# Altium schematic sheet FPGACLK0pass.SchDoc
size D
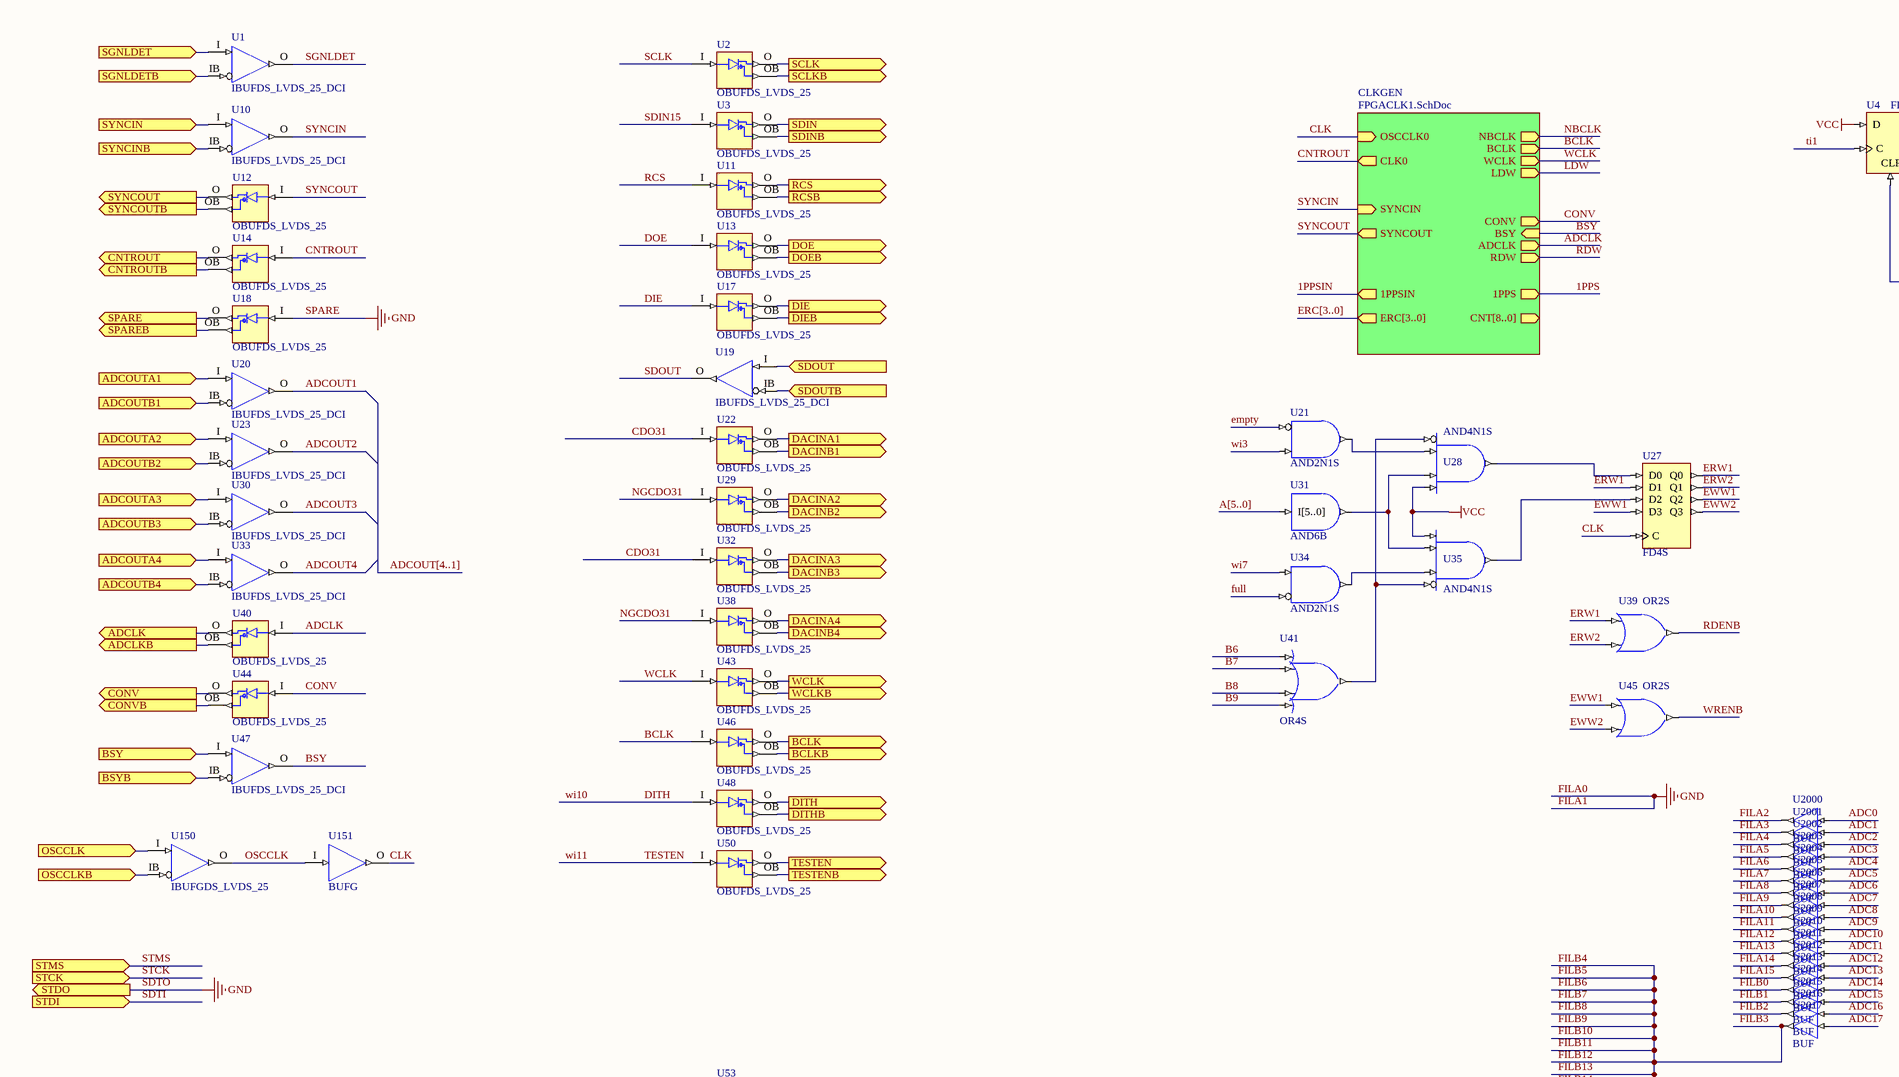
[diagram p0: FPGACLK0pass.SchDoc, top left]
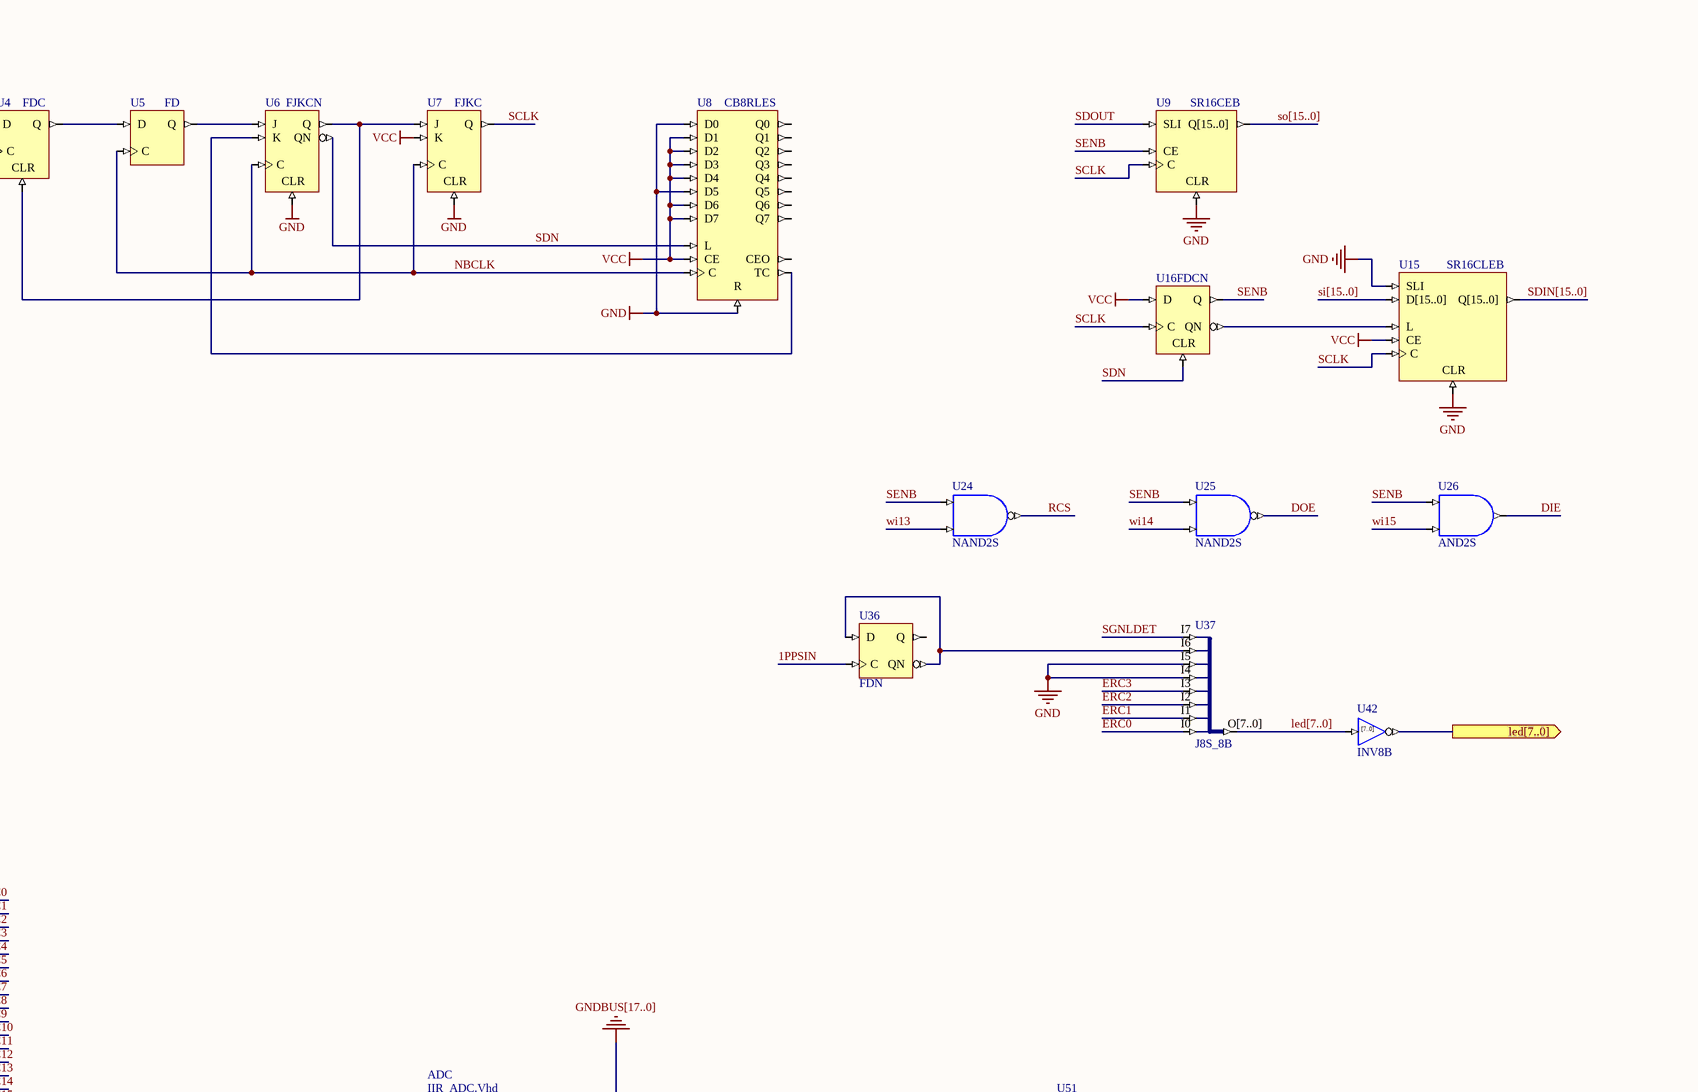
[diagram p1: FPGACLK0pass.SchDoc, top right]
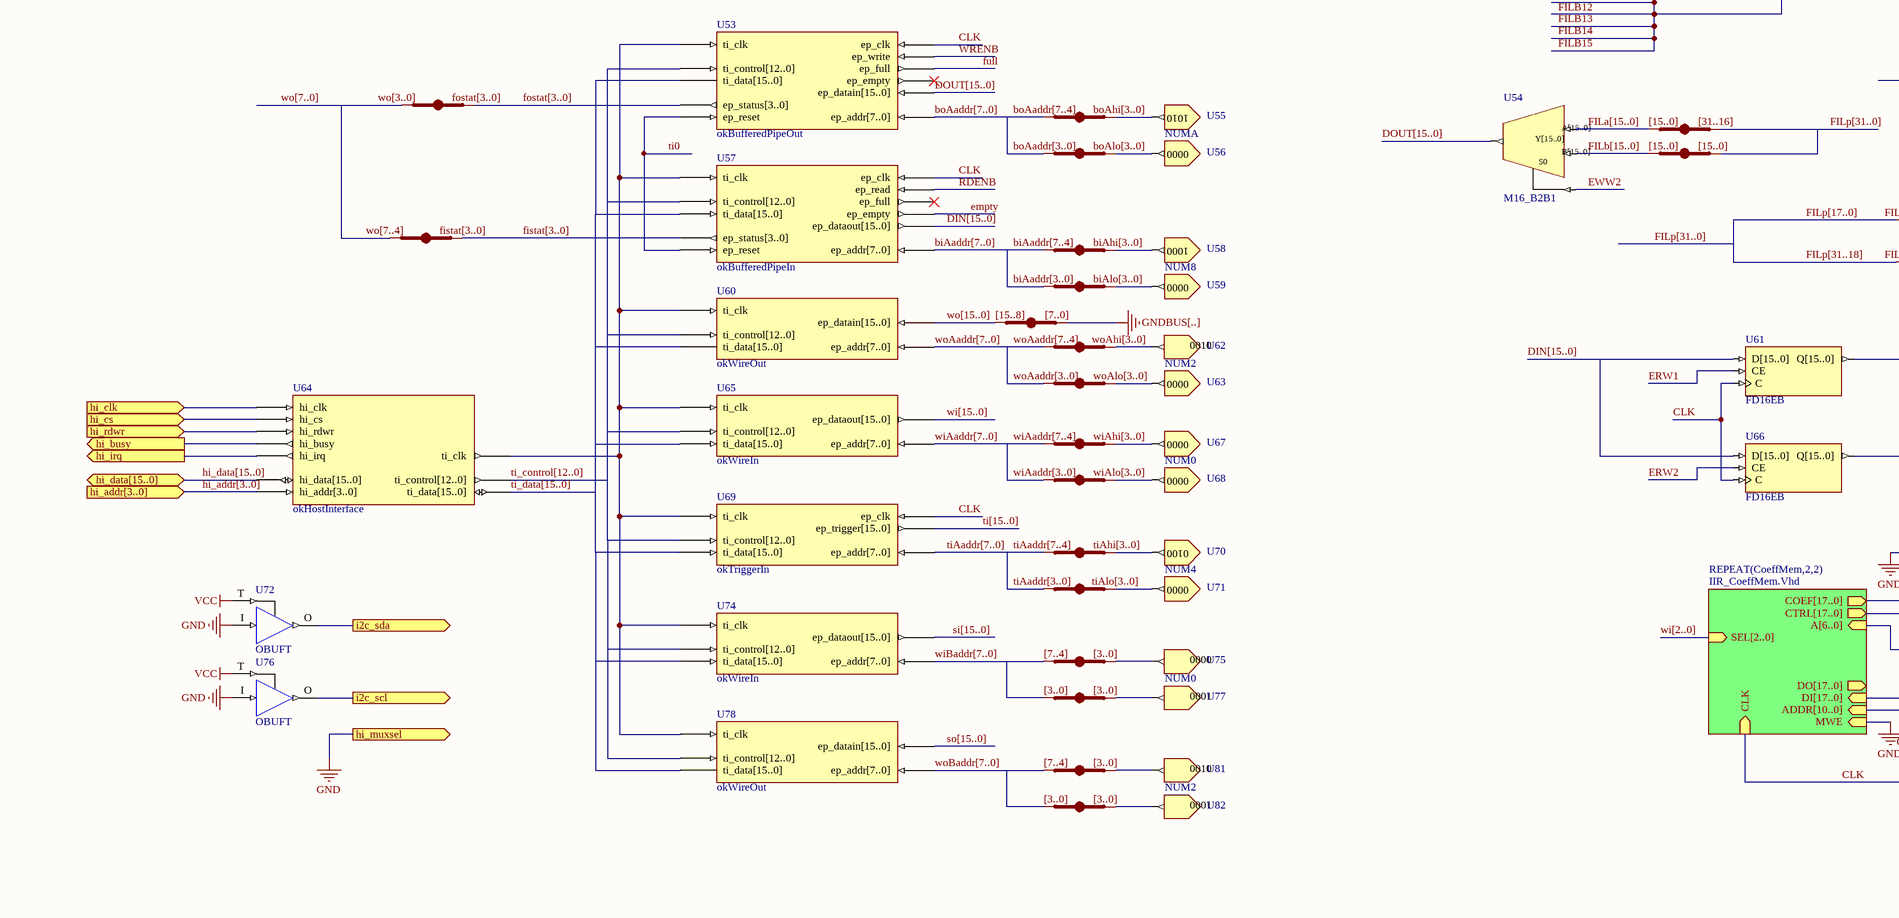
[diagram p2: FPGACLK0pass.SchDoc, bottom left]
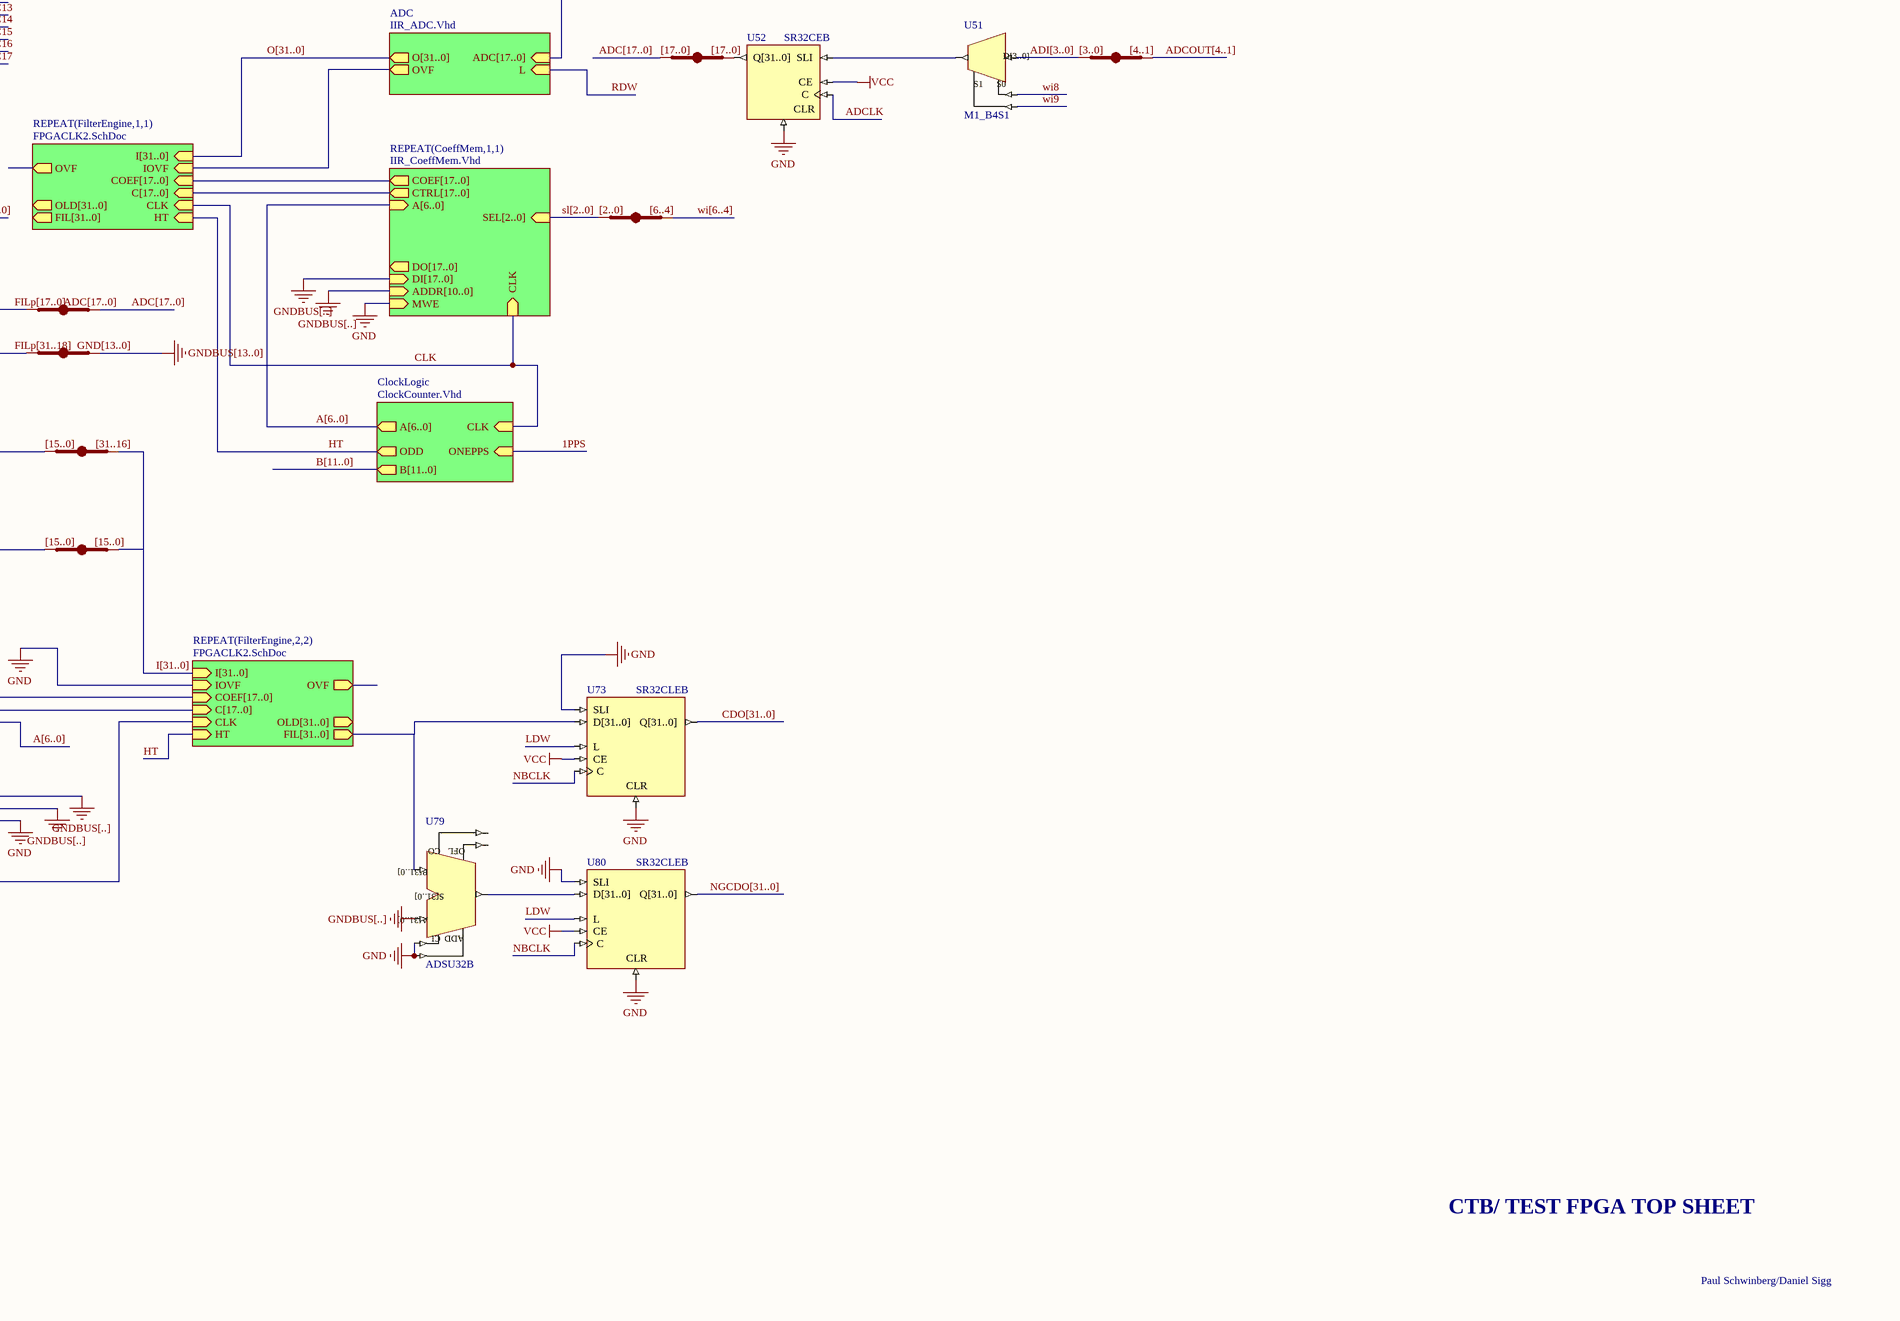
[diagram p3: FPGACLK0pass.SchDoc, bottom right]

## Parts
(Parts that share a designator on the sheet are numbered #1, #2 ... from top to bottom, then left to right.)
JB_AUTO?#1  IndexA: FILp[17..0]  IndexB: ADC[17..0]  (hidden comment: JB)
JB_AUTO?#2  IndexA: FILp[31..18]  IndexB: GND[13..0]  (hidden comment: JB)
JB_C1  IndexA: [17..0]  (hidden comment: JB)
JB_C2  IndexA: [3..0]  IndexB: [4..1]  (hidden comment: JB)
JB_C3  IndexA: wo[3..0]  IndexB: fostat[3..0]  (hidden comment: JB)
JB_C4  IndexA: boAaddr[7..4]  IndexB: boAhi[3..0]  (hidden comment: JB)
JB_C5  IndexA: [15..0]  IndexB: [31..16]  (hidden comment: JB)
JB_C6  IndexA: [2..0]  IndexB: [6..4]  (hidden comment: JB)
JB_C7  IndexA: boAaddr[3..0]  IndexB: boAlo[3..0]  (hidden comment: JB)
JB_C8  IndexA: [15..0]  (hidden comment: JB)
JB_C9  IndexA: wo[7..4]  IndexB: fistat[3..0]  (hidden comment: JB)
JB_C10  IndexA: biAaddr[7..4]  IndexB: biAhi[3..0]  (hidden comment: JB)
JB_C11  IndexA: biAaddr[3..0]  IndexB: biAlo[3..0]  (hidden comment: JB)
JB_C12#1  IndexA: [15..8]  IndexB: [7..0]  (hidden comment: JB)
JB_C12#2  IndexA: [15..0]  IndexB: [31..16]  (hidden comment: JB)
JB_C13  IndexA: woAaddr[7..4]  IndexB: woAhi[3..0]  (hidden comment: JB)
JB_C15  IndexA: woAaddr[3..0]  IndexB: woAlo[3..0]  (hidden comment: JB)
JB_C16  IndexA: wiAaddr[7..4]  IndexB: wiAhi[3..0]  (hidden comment: JB)
JB_C17  IndexA: [15..0]  (hidden comment: JB)
JB_C18  IndexA: wiAaddr[3..0]  IndexB: wiAlo[3..0]  (hidden comment: JB)
JB_C19  IndexA: tiAaddr[7..4]  IndexB: tiAhi[3..0]  (hidden comment: JB)
JB_C20  IndexA: tiAaddr[3..0]  IndexB: tiAlo[3..0]  (hidden comment: JB)
JB_C21  IndexA: [7..4]  IndexB: [3..0]  (hidden comment: JB)
JB_C22  IndexA: [3..0]  (hidden comment: JB)
JB_C23  IndexA: [7..4]  IndexB: [3..0]  (hidden comment: JB)
JB_C24  IndexA: [3..0]  (hidden comment: JB)
U1  IBUFDS_LVDS_25_DCI
U2  OBUFDS_LVDS_25
U3  OBUFDS_LVDS_25
U4  FDC
U5  FD
U6  FJKCN
U7  FJKC
U8  CB8RLES
U9  SR16CEB
U10  IBUFDS_LVDS_25_DCI
U11  OBUFDS_LVDS_25
U12  OBUFDS_LVDS_25
U13  OBUFDS_LVDS_25
U14  OBUFDS_LVDS_25
U15  SR16CLEB
U16  FDCN
U17  OBUFDS_LVDS_25
U18  OBUFDS_LVDS_25
U19  IBUFDS_LVDS_25_DCI
U20  IBUFDS_LVDS_25_DCI
U21  AND2N1S
U22  OBUFDS_LVDS_25
U23  IBUFDS_LVDS_25_DCI
U24  NAND2S
U25  NAND2S
U26  AND2S
U27  FD4S
U28  AND4N1S
U29  OBUFDS_LVDS_25
U30  IBUFDS_LVDS_25_DCI
U31  AND6B
U32  OBUFDS_LVDS_25
U33  IBUFDS_LVDS_25_DCI
U34  AND2N1S
U35  AND4N1S
U36  FDN
U37  J8S_8B
U38  OBUFDS_LVDS_25
U39  OR2S
U40  OBUFDS_LVDS_25
U41  OR4S
U42  INV8B
U43  OBUFDS_LVDS_25
U44  OBUFDS_LVDS_25
U45  OR2S
U46  OBUFDS_LVDS_25
U47  IBUFDS_LVDS_25_DCI
U48  OBUFDS_LVDS_25
U50  OBUFDS_LVDS_25
U51  M1_B4S1
U52  SR32CEB
U53  okBufferedPipeOut
U54  M16_B2B1
U55  NUMA
U56  NUM0  (value not drawn)
U57  okBufferedPipeIn
U58  NUM8
U59  NUM0  (value not drawn)
U60  okWireOut
U61  FD16EB
U62  NUM2
U63  NUM0  (value not drawn)
U64  okHostInterface
U65  okWireIn
U66  FD16EB
U67  NUM0
U68  NUM0  (value not drawn)
U69  okTriggerIn
U70  NUM4
U71  NUM0  (value not drawn)
U72  OBUFT
U73  SR32CLEB
U74  okWireIn
U75  NUM0
U76  OBUFT
U77  NUM1  (value not drawn)
U78  okWireOut
U79  ADSU32B
U80  SR32CLEB
U81  NUM2
U82  NUM1  (value not drawn)
U150  IBUFGDS_LVDS_25
U151  BUFG
U2000  BUF
U2001  BUF
U2002  BUF
U2003  BUF
U2004  BUF
U2005  BUF
U2006  BUF
U2007  BUF
U2008  BUF
U2009  BUF
U2010  BUF
U2011  BUF
U2012  BUF
U2013  BUF
U2014  BUF
U2015  BUF
U2016  BUF
U2017  BUF

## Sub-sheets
ADC = IIR_ADC.Vhd: ADC[17..0] (in), O[31..0] (out), L (in), OVF (out)
CLKGEN = FPGACLK1.SchDoc: SYNCIN (in), OSCCLK0 (in), CLK0 (out), SYNCOUT (out), BCLK (out), WCLK (out), LDW (out), CONV (out), BSY (in), ADCLK (out), RDW (out), NBCLK (out), 1PPS (out), 1PPSIN (out), ERC[3..0] (out), CNT[8..0] (out)
ClockLogic = ClockCounter.Vhd: CLK (in), ONEPPS (in), A[6..0] (out), ODD (out), B[11..0] (out)
REPEAT(CoeffMem,1,1) = IIR_CoeffMem.Vhd: CLK (in), A[6..0] (in), COEF[17..0] (out), CTRL[17..0] (out), SEL[2..0] (in), DI[17..0] (in), DO[17..0] (out), MWE (in), ADDR[10..0] (in)
REPEAT(CoeffMem,2,2) = IIR_CoeffMem.Vhd: CLK (in), A[6..0] (in), COEF[17..0] (out), CTRL[17..0] (out), SEL[2..0] (in), DI[17..0] (in), DO[17..0] (out), MWE (in), ADDR[10..0] (in)
REPEAT(FilterEngine,1,1) = FPGACLK2.SchDoc: CLK (in), FIL[31..0] (out), I[31..0] (in), C[17..0] (in), COEF[17..0] (in), HT (in), OLD[31..0] (out), OVF (out), IOVF (in)
REPEAT(FilterEngine,2,2) = FPGACLK2.SchDoc: CLK (in), FIL[31..0] (out), I[31..0] (in), C[17..0] (in), COEF[17..0] (in), HT (in), OLD[31..0] (out), OVF (out), IOVF (in)

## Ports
ADCLK (out), ADCLKB (out), ADCOUTA1 (in), ADCOUTA2 (in), ADCOUTA3 (in), ADCOUTA4 (in), ADCOUTB1 (in), ADCOUTB2 (in), ADCOUTB3 (in), ADCOUTB4 (in), BCLK (out), BCLKB (out), BSY (in), BSYB (in), CNTROUT (out), CNTROUTB (out), CONV (out), CONVB (out), DACINA1 (out), DACINA2 (out), DACINA3 (out), DACINA4 (out), DACINB1 (out), DACINB2 (out), DACINB3 (out), DACINB4 (out), DIE (out), DIEB (out), DITH (out), DITHB (out), DOE (out), DOEB (out), hi_addr[3..0] (in), hi_busy (out), hi_clk (in), hi_cs (in), hi_data[15..0] (bidir), hi_irq (out), hi_muxsel (out), hi_rdwr (in), i2c_scl (out), i2c_sda (out), led[7..0] (out), OSCCLK (in), OSCCLKB (in), RCS (out), RCSB (out), SCLK (out), SCLKB (out), SDIN (out), SDINB (out), SDOUT (in), SDOUTB (in), SGNLDET (in), SGNLDETB (in), SPARE (out), SPAREB (out), STCK (in), STDI (in), STDO (out), STMS (in), SYNCIN (in), SYNCINB (in), SYNCOUT (out), SYNCOUTB (out), TESTEN (out), TESTENB (out), WCLK (out), WCLKB (out)

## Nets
FILA0: U6.CLR U7.CLR U8.D0 U8.D5 U8.R U9.CLR U15.CLR U15.SLI U18.I U37.I4 U37.I5 U52.CLR U72.I U73.CLR U73.SLI U76.I U79.ADD U79.CI U80.CLR U80.SLI ; port hi_muxsel, port STDO, sheet REPEAT(CoeffMem,1,1)/MWE, sheet REPEAT(FilterEngine,2,2)/IOVF, sheet REPEAT(CoeffMem,2,2)/MWE  [also labelled FILA1, GND, SDTO, SPARE]
GNDBUS[..]: U79.A[31..0]
VCC: U4.D U7.K U8.CE U8.D1 U8.D2 U8.D3 U8.D4 U8.D6 U8.D7 U15.CE U16.D U28.I3 U35.I3 U52.CE U72.T U73.CE U76.T U80.CE
1PPS: sheet ClockLogic/ONEPPS, sheet CLKGEN/1PPS
1PPSIN: U36.C ; sheet CLKGEN/1PPSIN
ADC0: U2000.I
ADC1: U2001.I
ADC2: U2002.I
ADC3: U2003.I
ADC4: U2004.I
ADC5: U2005.I
ADC6: U2006.I
ADC7: U2007.I
ADC8: U2008.I
ADC9: U2009.I
ADC10: U2010.I
ADC11: U2011.I
ADC12: U2012.I
ADC13: U2013.I
ADC14: U2014.I
ADC15: U2015.I
ADC16: U2016.I
ADC17: U2017.I
ADCLK: U40.O ; port ADCLK
ADCLK: U40.I U52.C ; sheet CLKGEN/ADCLK  [a separate net that carries the same name]
ADCLKB: U40.OB ; port ADCLKB
ADCOUT1: U20.O
ADCOUT2: U23.O
ADCOUT3: U30.O
ADCOUT4: U33.O
ADCOUTA1: U20.I ; port ADCOUTA1
ADCOUTA2: U23.I ; port ADCOUTA2
ADCOUTA3: U30.I ; port ADCOUTA3
ADCOUTA4: U33.I ; port ADCOUTA4
ADCOUTB1: U20.IB ; port ADCOUTB1
ADCOUTB2: U23.IB ; port ADCOUTB2
ADCOUTB3: U30.IB ; port ADCOUTB3
ADCOUTB4: U33.IB ; port ADCOUTB4
B6: U41.I0
B7: U41.I1
B8: U41.I2
B9: U41.I3
BCLK: U46.O ; port BCLK
BCLK: U46.I ; sheet CLKGEN/BCLK  [a separate net that carries the same name]
BCLKB: U46.OB ; port BCLKB
BSY: U47.O ; sheet CLKGEN/BSY
BSY: U47.I ; port BSY  [a separate net that carries the same name]
BSYB: U47.IB ; port BSYB
CDO31: U22.I U32.I
CLK: U27.C U53.ep_clk U57.ep_clk U61.C U66.C U69.ep_clk U151.O ; sheet REPEAT(FilterEngine,1,1)/CLK, sheet ClockLogic/CLK, sheet REPEAT(CoeffMem,1,1)/CLK, sheet REPEAT(FilterEngine,2,2)/CLK, sheet REPEAT(CoeffMem,2,2)/CLK, sheet CLKGEN/OSCCLK0
CNTROUT: U14.O ; port CNTROUT
CNTROUT: U14.I ; sheet CLKGEN/CLK0  [a separate net that carries the same name]
CNTROUTB: U14.OB ; port CNTROUTB
CONV: U44.O ; port CONV
CONV: U44.I ; sheet CLKGEN/CONV  [a separate net that carries the same name]
CONVB: U44.OB ; port CONVB
DACINA1: U22.O ; port DACINA1
DACINA2: U29.O ; port DACINA2
DACINA3: U32.O ; port DACINA3
DACINA4: U38.O ; port DACINA4
DACINB1: U22.OB ; port DACINB1
DACINB2: U29.OB ; port DACINB2
DACINB3: U32.OB ; port DACINB3
DACINB4: U38.OB ; port DACINB4
DIE: U17.O ; port DIE
DIE: U17.I U26.O  [a separate net that carries the same name]
DIEB: U17.OB ; port DIEB
DITH: U48.O ; port DITH
DITH: U48.I  [also labelled wi10]  [a separate net that carries the same name]
DITHB: U48.OB ; port DITHB
DOE: U13.O ; port DOE
DOE: U13.I U25.O  [a separate net that carries the same name]
DOEB: U13.OB ; port DOEB
empty: U21.I0 U57.ep_empty
ERC0: U37.I0
ERC1: U37.I1
ERC2: U37.I2
ERC3: U37.I3
ERW1: U27.D1 U27.Q0 U39.I0 U61.CE
ERW2: U27.Q1 U39.I1 U66.CE
EWW1: U27.D3 U27.Q2 U45.I0
EWW2: U27.Q3 U45.I1 U54.S0
FILA2: U2000.O
FILA3: U2001.O
FILA4: U2002.O
FILA5: U2003.O
FILA6: U2004.O
FILA7: U2005.O
FILA8: U2006.O
FILA9: U2007.O
FILA10: U2008.O
FILA11: U2009.O
FILA12: U2010.O
FILA13: U2011.O
FILA14: U2012.O
FILA15: U2013.O
FILB0: U2014.O
FILB1: U2015.O
FILB2: U2016.O
FILB10: U2017.O  [also labelled FILB11, FILB12, FILB13, FILB14, FILB15, FILB3, FILB4, FILB5, FILB6, FILB7, FILB8, FILB9]
full: U34.I0 U53.ep_full
hi_busy: U64.hi_busy ; port hi_busy
hi_clk: U64.hi_clk ; port hi_clk
hi_cs: U64.hi_cs ; port hi_cs
hi_irq: U64.hi_irq ; port hi_irq
hi_rdwr: U64.hi_rdwr ; port hi_rdwr
HT: sheet REPEAT(FilterEngine,1,1)/HT, sheet ClockLogic/ODD, sheet REPEAT(FilterEngine,2,2)/HT
i2c_scl: U76.O ; port i2c_scl
i2c_sda: U72.O ; port i2c_sda
LDW: U73.L U80.L ; sheet CLKGEN/LDW
NBCLK: U5.C U6.C U7.C U8.C U73.C U80.C ; sheet CLKGEN/NBCLK
NGCDO31: U29.I U38.I
OSCCLK: U150.O U151.I
OSCCLK: U150.I ; port OSCCLK  [a separate net that carries the same name]
OSCCLKB: U150.IB ; port OSCCLKB
RCS: U11.O ; port RCS
RCS: U11.I U24.O  [a separate net that carries the same name]
RCSB: U11.OB ; port RCSB
RDENB: U39.O U57.ep_read
RDW: sheet ADC/L, sheet CLKGEN/RDW
SCLK: U2.O ; port SCLK
SCLK: U2.I U7.Q U9.C U15.C U16.C  [a separate net that carries the same name]
SCLKB: U2.OB ; port SCLKB
SDIN: U3.O ; port SDIN
SDIN15: U3.I
SDINB: U3.OB ; port SDINB
SDN: U6.QN U8.L U16.CLR
SDOUT: U9.SLI U19.O
SDOUT: U19.I ; port SDOUT  [a separate net that carries the same name]
SDOUTB: U19.IB ; port SDOUTB
SENB: U9.CE U16.Q U24.I0 U25.I0 U26.I0
SGNLDET: U1.O U37.I7
SGNLDET: U1.I ; port SGNLDET  [a separate net that carries the same name]
SGNLDETB: U1.IB ; port SGNLDETB
SPARE: U18.O ; port SPARE
SPAREB: U18.OB ; port SPAREB
SYNCIN: U10.O ; sheet CLKGEN/SYNCIN
SYNCIN: U10.I ; port SYNCIN  [a separate net that carries the same name]
SYNCINB: U10.IB ; port SYNCINB
SYNCOUT: U12.O ; port SYNCOUT
SYNCOUT: U12.I ; sheet CLKGEN/SYNCOUT  [a separate net that carries the same name]
SYNCOUTB: U12.OB ; port SYNCOUTB
TESTEN: U50.O ; port TESTEN
TESTEN: U50.I  [also labelled wi11]  [a separate net that carries the same name]
TESTENB: U50.OB ; port TESTENB
ti0: U53.ep_reset U57.ep_reset
ti1: U4.C
WCLK: U43.O ; port WCLK
WCLK: U43.I ; sheet CLKGEN/WCLK  [a separate net that carries the same name]
WCLKB: U43.OB ; port WCLKB
wi3: U21.I1
wi7: U34.I1
wi8: U51.S0
wi9: U51.S1
wi13: U24.I1
wi14: U25.I1
wi15: U26.I1
WRENB: U45.O U53.ep_write
NetJB_C1_B[0..0]: JB_C1.B[0..0] U52.Q[31..0]
NetU4_CLR: U4.CLR U6.Q U7.J
NetU4_Q: U4.Q U5.D
NetU5_Q: U5.Q U6.J
NetU6_K: U6.K U8.TC
NetU15_L: U15.L U16.QN
NetU21_O: U21.O U28.I1
NetU27_D0: U27.D0 U28.O
NetU27_D2: U27.D2 U35.O
NetU28_I0: U28.I0 U35.I0 U41.O
NetU28_I2: U28.I2 U31.O U35.I2
NetU34_O: U34.O U35.I1
NetU36_D: U36.D U36.QN U37.I6
NetU51_O: U51.O U52.SLI
NetU53_ti_clk: U53.ti_clk U57.ti_clk U60.ti_clk U64.ti_clk U65.ti_clk U69.ti_clk U74.ti_clk U78.ti_clk
(unnamed): sheet REPEAT(FilterEngine,1,1)/IOVF, sheet ADC/OVF

Not connected (* = marked no-connect by the designer): JB_AUTO?#1 A[0..0] B[0..0]; JB_AUTO?#2 A[0..0] B[0..0]; JB_C1 A[0..0]; JB_C2 A[0..0] B[0..0]; JB_C3 A[0..0] B[0..0]; JB_C4 A[0..0] B[0..0]; JB_C5 A[0..0] B[0..0]; JB_C6 A[0..0] B[0..0]; JB_C7 A[0..0] B[0..0]; JB_C8 A[0..0] B[0..0]; JB_C9 A[0..0] B[0..0]; JB_C10 A[0..0] B[0..0]; JB_C11 A[0..0] B[0..0]; JB_C12#1 A[0..0] B[0..0]; JB_C12#2 A[0..0] B[0..0]; JB_C13 A[0..0] B[0..0]; JB_C15 A[0..0] B[0..0]; JB_C16 A[0..0] B[0..0]; JB_C17 A[0..0] B[0..0]; JB_C18 A[0..0] B[0..0]; JB_C19 A[0..0] B[0..0]; JB_C20 A[0..0] B[0..0]; JB_C21 A[0..0] B[0..0]; JB_C22 A[0..0] B[0..0]; JB_C23 A[0..0] B[0..0]; JB_C24 A[0..0] B[0..0]; U8 CEO Q0 Q1 Q2 Q3 Q4 Q5 Q6 Q7; U9 Q[15..0]; U15 D[15..0] Q[15..0]; U31 I[5..0]; U36 Q; U37 O[7..0]; U42 I[7..0] O[7..0]; U51 D[3..0]; U53 ep_addr[7..0] ep_datain[15..0] ep_empty* ep_status[3..0] ti_control[12..0] ti_data[15..0]; U54 A[15..0] B[15..0] Y[15..0]; U55 O[3..0]; U56 O[3..0]; U57 ep_addr[7..0] ep_dataout[15..0] ep_full* ep_status[3..0] ti_control[12..0] ti_data[15..0]; U58 O[3..0]; U59 O[3..0]; U60 ep_addr[7..0] ep_datain[15..0] ti_control[12..0] ti_data[15..0]; U61 D[15..0] Q[15..0]; U62 O[3..0]; U63 O[3..0]; U64 hi_addr[3..0] hi_data[15..0] ti_control[12..0] ti_data[15..0]; U65 ep_addr[7..0] ep_dataout[15..0] ti_control[12..0] ti_data[15..0]; U66 D[15..0] Q[15..0]; U67 O[3..0]; U68 O[3..0]; U69 ep_addr[7..0] ep_trigger[15..0] ti_control[12..0] ti_data[15..0]; U70 O[3..0]; U71 O[3..0]; U73 D[31..0] Q[31..0]; U74 ep_addr[7..0] ep_dataout[15..0] ti_control[12..0] ti_data[15..0]; U75 O[3..0]; U77 O[3..0]; U78 ep_addr[7..0] ep_datain[15..0] ti_control[12..0] ti_data[15..0]; U79 B[31..0] CO OFL S[31..0]; U80 D[31..0] Q[31..0]; U81 O[3..0]; U82 O[3..0]

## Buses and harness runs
bus A[5..0]
bus A[6..0] = sheet ClockLogic/A[6..0] = sheet REPEAT(CoeffMem,1,1)/A[6..0]
bus A[6..0] = sheet REPEAT(CoeffMem,2,2)/A[6..0]
bus ADC[17..0]
bus ADCOUT[4..1]
bus ADI[3..0]
bus B[11..0] = sheet ClockLogic/B[11..0]
bus biAaddr[7..0]
bus boAaddr[7..0]
bus CDO[31..0]
bus DIN[15..0]
bus DOUT[15..0]
bus ERC[3..0] = sheet CLKGEN/ERC[3..0]
bus FILa[15..0]
bus FILb[15..0]
bus FILp[17..0] = FILp[31..0] = FILp[31..18]
bus FILp[31..0]
bus fistat[3..0]
bus fostat[3..0]
bus hi_addr[3..0] = port hi_addr[3..0]
bus hi_data[15..0] = port hi_data[15..0]
bus I[31..0] = sheet REPEAT(FilterEngine,2,2)/I[31..0]
bus led[7..0]
bus NGCDO[31..0]
bus O[31..0] = sheet ADC/O[31..0] = sheet REPEAT(FilterEngine,1,1)/I[31..0]
bus SDIN[15..0]
bus sheet REPEAT(CoeffMem,1,1)/COEF[17..0] = sheet REPEAT(FilterEngine,1,1)/COEF[17..0]
bus sheet REPEAT(CoeffMem,1,1)/CTRL[17..0] = sheet REPEAT(FilterEngine,1,1)/C[17..0]
bus sheet REPEAT(CoeffMem,2,2)/COEF[17..0] = sheet REPEAT(FilterEngine,2,2)/COEF[17..0]
bus sheet REPEAT(CoeffMem,2,2)/CTRL[17..0] = sheet REPEAT(FilterEngine,2,2)/C[17..0]
bus si[15..0]
bus sl[2..0] = sheet REPEAT(CoeffMem,1,1)/SEL[2..0]
bus so[15..0]
bus ti[15..0]
bus ti_control[12..0]
bus ti_data[15..0]
bus tiAaddr[7..0]
bus wi[2..0] = sheet REPEAT(CoeffMem,2,2)/SEL[2..0]
bus wi[6..4]
bus wi[15..0]
bus wiAaddr[7..0]
bus wiBaddr[7..0]
bus wo[7..0]
bus wo[15..0]
bus woAaddr[7..0]
bus woBaddr[7..0]

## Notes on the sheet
- CTB/ TEST FPGA TOP SHEET
- Paul Schwinberg/Daniel Sigg
- Labels drawn without touching a wire or pin: GNDBUS[13..0], GNDBUS[17..0], GNDBUS[..]

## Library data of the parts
JB_AUTO?#1 JB_AUTO?#2 JB_C1-JB_C11 JB_C12#1 JB_C12#2 JB_C13 JB_C15-JB_C24 = JB: System BUS Joiner
U1 U10 U19 U20 U23 U30 U33 U47 = IBUFDS_LVDS_25_DCI: Differential Signaling Input Buffer with LVDS_25_DCI I/O Interface; FPGAVendor: Xilinx
U2 U3 U11-U14 U17 U18 U22 U29 U32 U38 U40 U43 U44 U46 U48 U50 = OBUFDS_LVDS_25: Differential Signaling Output Buffer with LVDS_25 I/O Interface; FPGAVendor: Xilinx
U4 = FDC: D-Type Flip-Flop with Asynchronous Clear; SubClass: FD; ClockTrigger: Rising; ArchiveName: GENERIC; VHDLIB_SIM: GENERIC_LIB
U5 = FD: D-Type Flip-Flop; ClockTrigger: Rising; ArchiveName: GENERIC; VHDLIB_SIM: GENERIC_LIB
U6 = FJKCN: J-K Flip-Flop with Asynchronous Clear and Inverted and Non-Inverted Outputs; SubClass: JK; ClockTrigger: Rising; ArchiveName: GENERIC; VHDLIB_SIM: GENERIC_LIB
U7 = FJKC: J-K Flip-Flop with Asynchronous Clear; SubClass: JK; ClockTrigger: Rising; ArchiveName: GENERIC; VHDLIB_SIM: GENERIC_LIB
U8 = CB8RLES: 8-Bit Loadable Cascadable Binary Counter with Clock Enable and Synchronous Reset, Single Pin Version; ClockTrigger: Rising; Enable: High; Loadable: True; PortSize: 8; ArchiveName: GENERIC; VHDLIB_SIM: GENERIC_LIB
U9 = SR16CEB: 16-Bit Serial-In Parallel-Out Shift Registers with Clock Enable and Asynchronous Clear, Bus Version; XilinxEquivalent: SR16CE; ClockTrigger: Rising; Enable: High; PortSize: 16; ArchiveName: GENERIC; VHDLIB_SIM: GENERIC_LIB
U15 = SR16CLEB: 16-Bit Loadable Serial/Parallel-In Parallel-Out Shift Registers with Clock Enable and Asynchronous Clear, Bus Version; ClockTrigger: Rising; Enable: High; Loadable: True; PortSize: 16; ArchiveName: GENERIC; VHDLIB_SIM: GENERIC_LIB
U16 = FDCN: D-Type Flip-Flop with Asynchronous Clear and Inverted and Non-Inverted Outputs; SubClass: FD; ClockTrigger: Rising; ArchiveName: GENERIC; VHDLIB_SIM: GENERIC_LIB
U21 U34 = AND2N1S: 2-Input AND Gate with Active Low A Input, Single Pin Version; XilinxEquivalent: AND2B1; FunctionalClass: Logic Primitive; PortSize: 2; ArchiveName: GENERIC; VHDLIB_SIM: GENERIC_LIB
U24 U25 = NAND2S: 2-Input NAND Gate, Single Pin Version; XilinxEquivalent: NAND2; FunctionalClass: Logic Primitive; PortSize: 2; ArchiveName: GENERIC; VHDLIB_SIM: GENERIC_LIB
U26 = AND2S: 2-Input AND Gate, Single Pin Version; XilinxEquivalent: AND2; FunctionalClass: Logic Primitive; PortSize: 2; ArchiveName: GENERIC; VHDLIB_SIM: GENERIC_LIB
U27 = FD4S: 4-Bit D-Type Flip-Flop, Single Pin Version; XilinxEquivalent: FD4; SubClass: FD; ClockTrigger: Rising; PortSize: 4; ArchiveName: GENERIC; VHDLIB_SIM: GENERIC_LIB
U28 U35 = AND4N1S: 4-Input AND Gate with Active Low A Input, Single Pin Version; XilinxEquivalent: AND4B1; FunctionalClass: Logic Primitive; PortSize: 4; ArchiveName: GENERIC; VHDLIB_SIM: GENERIC_LIB
U31 = AND6B: 6-Input AND Gate, Bus Version; FunctionalClass: Logic Primitive; PortSize: 6; ArchiveName: GENERIC; VHDLIB_SIM: GENERIC_LIB
U36 = FDN: D-Type Flip-Flop with Inverted and Non-Inverted Outputs; SubClass: FD; ClockTrigger: Rising; ArchiveName: GENERIC; VHDLIB_SIM: GENERIC_LIB
U37 = J8S_8B: 8 Single pin inputs to single 8-Bit output bus; FunctionalClass: Bus Joiner; PortSize: 8; ArchiveName: GENERIC; VHDLIB_SIM: GENERIC_LIB
U39 U45 = OR2S: 2-Input OR Gate, Single Pin Version; XilinxEquivalent: OR2; FunctionalClass: Logic Primitive; PortSize: 2; ArchiveName: GENERIC; VHDLIB_SIM: GENERIC_LIB
U41 = OR4S: 4-Input OR Gate, Single Pin Version; XilinxEquivalent: OR4; FunctionalClass: Logic Primitive; PortSize: 4; ArchiveName: GENERIC; VHDLIB_SIM: GENERIC_LIB
U42 = INV8B: 8-Bit Inverter, Bus Version; XilinxEquivalent: INV8; FunctionalClass: Logic Primitive; SubClass: INV; PortSize: 8; ArchiveName: GENERIC; VHDLIB_SIM: GENERIC_LIB
U51 = M1_B4S1: 1x4-Bit Bus to 1x1-Single Wire Multiplexer; SubClass: BnS1; PortSize: 1; PortStyle: Bus Version; ArchiveName: GENERIC; VHDLIB_SIM: GENERIC_LIB
U52 = SR32CEB: 32-Bit Serial-In Parallel-Out Shift Registers with Clock Enable and Asynchronous Clear, Bus Version; ClockTrigger: Rising; Enable: High; PortSize: 32; ArchiveName: GENERIC; VHDLIB_SIM: GENERIC_LIB
U53 = okBufferedPipeOut: Opal Kelly FPGA Board Buffered Pipe Output Interface
U54 = M16_B2B1: 2x16-Bit Bus to 1x16-Bit Bus Multiplexer; SubClass: BnB1; PortSize: 16; ArchiveName: GENERIC; VHDLIB_SIM: GENERIC_LIB
U55 = NUMA: Number Connector A; FunctionalClass: Numeric Connector; PortSize: 4; PortStyle: Bus Version; ArchiveName: GENERIC; VHDLIB_SIM: GENERIC_LIB
U56 U59 U63 U67 U68 U71 U75 = NUM0: Number Connector 0; FunctionalClass: Numeric Connector; SubClass: 0; PortSize: 4; PortStyle: Bus Version; ArchiveName: GENERIC; VHDLIB_SIM: GENERIC_LIB
U57 = okBufferedPipeIn: Opal Kelly FPGA Board Buffered Pipe Input Interface
U58 = NUM8: Number Connector 8; FunctionalClass: Numeric Connector; SubClass: 8; PortSize: 4; PortStyle: Bus Version; ArchiveName: GENERIC; VHDLIB_SIM: GENERIC_LIB
U60 U78 = okWireOut: Opal Kelly FPGA Board Wire Output Interface
U61 U66 = FD16EB: 16-Bit D Flip-Flop with Clock Enable, Bus Version; SubClass: FD; ClockTrigger: Rising; Enable: High; PortSize: 16; ArchiveName: GENERIC; VHDLIB_SIM: GENERIC_LIB
U62 U81 = NUM2: Number Connector 2; FunctionalClass: Numeric Connector; SubClass: 2; PortSize: 4; PortStyle: Bus Version; ArchiveName: GENERIC; VHDLIB_SIM: GENERIC_LIB
U64 = okHostInterface: Opal Kelly FPGA Board Host Interface
U65 U74 = okWireIn: Opal Kelly FPGA Board Wire Input Interface
U69 = okTriggerIn: Opal Kelly FPGA Board Trigger Input Interface
U70 = NUM4: Number Connector 4; FunctionalClass: Numeric Connector; SubClass: 4; PortStyle: Bus Version; ArchiveName: GENERIC; VHDLIB_SIM: GENERIC_LIB
U72 U76 = OBUFT: Single 3-State Output Buffer with Active-Low Output Enable; FPGAVendor: Xilinx
U73 U80 = SR32CLEB: 32-Bit Loadable Serial/Parallel-In Parallel-Out Shift Registers with Clock Enable and Asynchronous Clear, Bus Version; ClockTrigger: Rising; Enable: High; Loadable: True; PortSize: 32; ArchiveName: GENERIC; VHDLIB_SIM: GENERIC_LIB
U77 U82 = NUM1: Number Connector 1; FunctionalClass: Numeric Connector; SubClass: 1; PortSize: 4; PortStyle: Bus Version; ArchiveName: GENERIC; VHDLIB_SIM: GENERIC_LIB
U79 = ADSU32B: 32-Bit Cascadable Full Adder/Subtracter with Signed and Unsigned Operations, Bus Version; FunctionalClass: Arithmetic Function; SubClass: ADSU; PortSize: 32; ArchiveName: GENERIC; VHDLIB_SIM: GENERIC_LIB
U150 = IBUFGDS_LVDS_25: Dedicated Differential Signaling Input Buffer with LVDS_25 I/O Interface; FPGAVendor: Xilinx
U151 = BUFG: Global Clock Buffer; FPGAVendor: Xilinx
U2000-U2017 = BUF: 1-bit General Purpose (Non-inverting) Buffer; ArchiveName: GENERIC; VHDLIB_SIM: GENERIC_LIB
